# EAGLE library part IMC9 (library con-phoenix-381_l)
Invertierter Mini-Combicon 3.81mm horizontal 9-polig IMC 1,5/9-G-3,81 (ohne Gegenstecker)
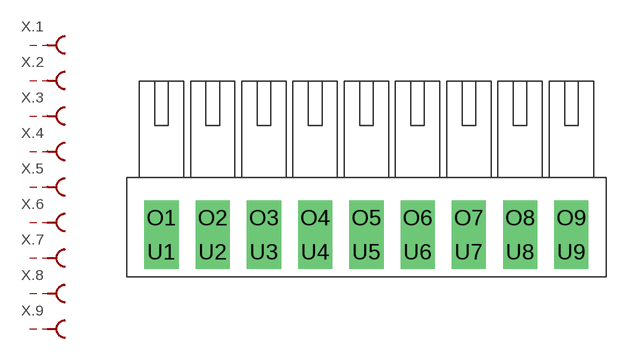
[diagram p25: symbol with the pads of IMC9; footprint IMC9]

Designator prefix X; gates .5=MCBU .4=MCBU .3=MCBU .2=MCBU .1=MCBU .6=MCBU .7=MCBU .8=MCBU .9=MCBU

## IMC9  [IMC9]
O1  .1:S  pas
O2  .2:S  pas
O3  .3:S  pas
O4  .4:S  pas
O5  .5:S  pas
O6  .6:S  pas
O7  .7:S  pas
O8  .8:S  pas
O9  .9:S  pas
U1  .1:SK  pas
U2  .2:SK  pas
U3  .3:SK  pas
U4  .4:SK  pas
U5  .5:SK  pas
U6  .6:SK  pas
U7  .7:SK  pas
U8  .8:SK  pas
U9  .9:SK  pas

## Footprint IMC9 (pad centres in mm)
Mini-Combicon 3.81mm horizontal 9-polig invertiert (ohne Gegenstecker)
drill 1.3 pad 2.54 square: O1 -15.24,1.27; O2 -11.43,1.27; O3 -7.62,1.27; O4 -3.81,1.27; O5 0,1.27; O6 3.81,1.27; O7 7.62,1.27; O8 11.43,1.27; O9 15.24,1.27; U1 -15.24,-1.27; U2 -11.43,-1.27; U3 -7.62,-1.27; U4 -3.81,-1.27; U5 0,-1.27; U6 3.81,-1.27; U7 7.62,-1.27; U8 11.43,-1.27; U9 15.24,-1.27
